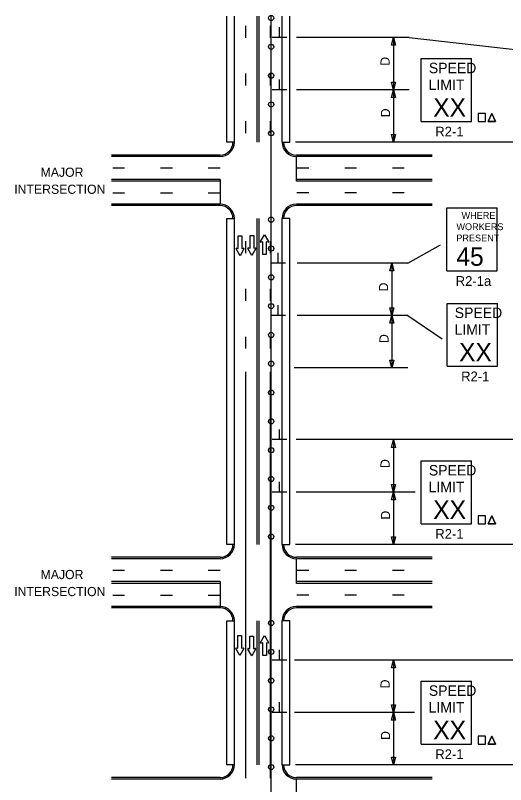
# Model space of a CAD drawing. Extents: x 16735 to 18480, y 5932 to 6927.
# Drawn here: x 16778 to 17153, y 6340 to 6927 of the extents above; entities that cross this region are included whole.
import ezdxf

# ---------------------------------------------------------------- set-up
doc = ezdxf.new("R2010")
doc.units = 0
for name, color, linetype in [('ALI_LEGAL_EX', 7, 'Continuous'), ('MT_SCRATCH_LEVEL_E', 7, 'Continuous'), ('PAVT_EDGE_EX', 7, 'Continuous'), ('TRAFFIC_SIGNS_PR', 7, 'Continuous'), ('TYPICAL_TEXT_DIMEN_PR', 7, 'Continuous')]:
    doc.layers.add(name, color=color, linetype=linetype)

msp = doc.modelspace()

# ---------------------------------------------------------------- linework, layer by layer
at = {"layer": 'ALI_LEGAL_EX'}
for p, q in [((16954.56, 6344.68), (16954.56, 6654.91)), ((16973.51, 6344.68), (16973.51, 6654.91))]:
    msp.add_line(p, q, dxfattribs=at)
for points in [[(16954.56, 6910.12), (16954.56, 6919.23)], [(16973.51, 6910.12), (16973.51, 6919.23)], [(16954.56, 6873.67), (16954.56, 6882.78)], [(16973.51, 6873.67), (16973.51, 6882.78)], [(16954.56, 6837.22), (16954.56, 6846.33)], [(16973.51, 6837.22), (16973.51, 6846.33)], [(16852.86, 6810.71), (16861.98, 6810.71)], [(16889.31, 6810.71), (16898.43, 6810.71)], [(16925.76, 6810.71), (16934.88, 6810.71)], [(16993.62, 6810.85), (17002.73, 6810.85)], [(17030.07, 6810.85), (17039.18, 6810.85)], [(17066.52, 6810.85), (17075.63, 6810.85)], [(16852.86, 6791.76), (16861.98, 6791.76)], [(16889.31, 6791.76), (16898.43, 6791.76)], [(16925.76, 6791.76), (16934.88, 6791.76)], [(16993.62, 6791.9), (17002.73, 6791.9)], [(17030.07, 6791.9), (17039.18, 6791.9)], [(17066.52, 6791.9), (17075.63, 6791.9)], [(16954.56, 6745.63), (16954.56, 6754.74)], [(16973.51, 6745.63), (16973.51, 6754.74)], [(16954.56, 6709.18), (16954.56, 6718.29)], [(16973.51, 6709.18), (16973.51, 6718.29)], [(16954.56, 6672.73), (16954.56, 6681.84)], [(16973.51, 6672.73), (16973.51, 6681.84)], [(16954.56, 6636.28), (16954.56, 6645.39)], [(16973.51, 6636.28), (16973.51, 6645.39)], [(16954.56, 6599.83), (16954.56, 6608.94)], [(16973.51, 6599.83), (16973.51, 6608.94)], [(16852.86, 6503.52), (16861.98, 6503.52)], [(16889.31, 6503.52), (16898.43, 6503.52)], [(16925.76, 6503.52), (16934.88, 6503.52)], [(16993.62, 6503.67), (17002.73, 6503.67)], [(17030.07, 6503.67), (17039.18, 6503.67)], [(17066.52, 6503.67), (17075.63, 6503.67)], [(16852.86, 6484.57), (16861.98, 6484.57)], [(16889.31, 6484.57), (16898.43, 6484.57)], [(16925.76, 6484.57), (16934.88, 6484.57)], [(16993.62, 6484.71), (17002.73, 6484.71)], [(17030.07, 6484.71), (17039.18, 6484.71)], [(17066.52, 6484.71), (17075.63, 6484.71)], [(16954.56, 6454.03), (16954.56, 6463.14)], [(16973.51, 6454.03), (16973.51, 6463.14)], [(16954.56, 6417.58), (16954.56, 6426.69)], [(16973.51, 6417.58), (16973.51, 6426.69)], [(16954.56, 6381.13), (16954.56, 6390.24)], [(16973.51, 6381.13), (16973.51, 6390.24)]]:
    msp.add_lwpolyline(points, dxfattribs=at)
at = {"layer": 'MT_SCRATCH_LEVEL_E'}
for p, q in [((16948.75, 6749.12), (16948.75, 6758.78)), ((16948.75, 6758.78), (16951.47, 6758.78)), ((16948.75, 6749.12), (16948.75, 6758.78)), ((16948.75, 6758.78), (16951.47, 6758.78)), ((16951.47, 6758.78), (16951.47, 6749.12)), ((16951.47, 6758.78), (16951.47, 6749.12)), ((16957.83, 6749.47), (16957.83, 6759.13)), ((16957.83, 6759.13), (16960.56, 6759.13)), ((16957.83, 6749.47), (16957.83, 6759.13)), ((16957.83, 6759.13), (16960.56, 6759.13)), ((16960.56, 6759.13), (16960.56, 6749.47)), ((16960.56, 6759.13), (16960.56, 6749.47)), ((16965.84, 6754.45), (16968.86, 6759.73)), ((16965.84, 6754.45), (16968.86, 6759.73)), ((16968.86, 6759.73), (16971.85, 6754.45)), ((16968.86, 6759.73), (16971.85, 6754.45)), ((16947.45, 6749.35), (16948.75, 6749.12)), ((16947.45, 6749.35), (16948.75, 6749.12)), ((16951.47, 6749.12), (16952.77, 6749.35)), ((16951.47, 6749.12), (16952.77, 6749.35)), ((16959.18, 6743.92), (16956.18, 6749.2)), ((16959.18, 6743.92), (16956.18, 6749.2)), ((16956.53, 6749.7), (16957.83, 6749.47)), ((16956.53, 6749.7), (16957.83, 6749.47)), ((16962.2, 6749.2), (16959.18, 6743.92)), ((16962.2, 6749.2), (16959.18, 6743.92)), ((16960.56, 6749.47), (16961.85, 6749.7)), ((16960.56, 6749.47), (16961.85, 6749.7)), ((16967.48, 6754.18), (16966.18, 6753.95)), ((16967.48, 6754.18), (16966.18, 6753.95)), ((16967.48, 6744.52), (16967.48, 6754.18)), ((16967.48, 6744.52), (16967.48, 6754.18)), ((16971.5, 6753.95), (16970.21, 6754.18)), ((16970.21, 6754.18), (16970.21, 6744.52)), ((16971.5, 6753.95), (16970.21, 6754.18)), ((16970.21, 6754.18), (16970.21, 6744.52)), ((16950.1, 6743.57), (16947.1, 6748.85)), ((16950.1, 6743.57), (16947.1, 6748.85)), ((16953.12, 6748.85), (16950.1, 6743.57)), ((16953.12, 6748.85), (16950.1, 6743.57)), ((16970.21, 6744.52), (16967.48, 6744.52)), ((16970.21, 6744.52), (16967.48, 6744.52)), ((16948.54, 6443.9), (16948.54, 6453.56)), ((16948.54, 6453.56), (16951.27, 6453.56)), ((16948.54, 6443.9), (16948.54, 6453.56)), ((16948.54, 6453.56), (16951.27, 6453.56)), ((16951.27, 6453.56), (16951.27, 6443.9)), ((16951.27, 6453.56), (16951.27, 6443.9)), ((16957.69, 6443.62), (16957.69, 6453.28)), ((16957.69, 6453.28), (16960.42, 6453.28)), ((16957.69, 6443.62), (16957.69, 6453.28)), ((16957.69, 6453.28), (16960.42, 6453.28)), ((16960.42, 6453.28), (16960.42, 6443.62)), ((16960.42, 6453.28), (16960.42, 6443.62)), ((16965.85, 6448.31), (16968.87, 6453.58)), ((16965.85, 6448.31), (16968.87, 6453.58)), ((16968.87, 6453.58), (16971.87, 6448.31)), ((16968.87, 6453.58), (16971.87, 6448.31)), ((16947.25, 6444.13), (16948.54, 6443.9)), ((16947.25, 6444.13), (16948.54, 6443.9)), ((16951.27, 6443.9), (16952.57, 6444.13)), ((16951.27, 6443.9), (16952.57, 6444.13)), ((16956.39, 6443.85), (16957.69, 6443.62)), ((16956.39, 6443.85), (16957.69, 6443.62)), ((16960.42, 6443.62), (16961.71, 6443.85)), ((16960.42, 6443.62), (16961.71, 6443.85)), ((16967.49, 6448.04), (16966.2, 6447.81)), ((16967.49, 6448.04), (16966.2, 6447.81)), ((16967.49, 6438.37), (16967.49, 6448.04)), ((16967.49, 6438.37), (16967.49, 6448.04)), ((16971.52, 6447.81), (16970.22, 6448.04)), ((16970.22, 6448.04), (16970.22, 6438.37)), ((16971.52, 6447.81), (16970.22, 6448.04)), ((16970.22, 6448.04), (16970.22, 6438.37)), ((16949.89, 6438.35), (16946.9, 6443.63)), ((16949.89, 6438.35), (16946.9, 6443.63)), ((16952.92, 6443.63), (16949.89, 6438.35)), ((16952.92, 6443.63), (16949.89, 6438.35)), ((16959.04, 6438.07), (16956.04, 6443.35)), ((16959.04, 6438.07), (16956.04, 6443.35)), ((16962.06, 6443.35), (16959.04, 6438.07)), ((16962.06, 6443.35), (16959.04, 6438.07)), ((16970.22, 6438.37), (16967.49, 6438.37)), ((16970.22, 6438.37), (16967.49, 6438.37))]:
    msp.add_line(p, q, dxfattribs=at)
for centre, start, end in [((16947.4, 6749.01), 80.03619, 209.57516), ((16947.4, 6749.01), 80.03619, 209.57516), ((16952.82, 6749.01), 330.22688, 99.96381), ((16952.82, 6749.01), 330.22688, 99.96381), ((16956.48, 6749.36), 80.03619, 209.57516), ((16956.48, 6749.36), 80.03619, 209.57516), ((16961.9, 6749.36), 330.22688, 99.96381), ((16961.9, 6749.36), 330.22688, 99.96381), ((16966.13, 6754.29), 150.22688, 279.96381), ((16966.13, 6754.29), 150.22688, 279.96381), ((16971.56, 6754.29), 260.03619, 29.57516), ((16971.56, 6754.29), 260.03619, 29.57516), ((16947.19, 6443.79), 80.03619, 209.57516), ((16947.19, 6443.79), 80.03619, 209.57516), ((16952.62, 6443.79), 330.22688, 99.96381), ((16952.62, 6443.79), 330.22688, 99.96381), ((16956.34, 6443.51), 80.03619, 209.57516), ((16956.34, 6443.51), 80.03619, 209.57516), ((16961.76, 6443.51), 330.22688, 99.96381), ((16961.76, 6443.51), 330.22688, 99.96381), ((16966.15, 6448.14), 150.22688, 279.96381), ((16966.15, 6448.14), 150.22688, 279.96381), ((16971.57, 6448.14), 260.03619, 29.57516), ((16971.57, 6448.14), 260.03619, 29.57516)]:
    msp.add_arc(centre, 0.337, start, end, dxfattribs=at)
at = {"layer": 'PAVT_EDGE_EX'}
for p, q in [((16939.98, 6830.39), (16939.98, 6926.6)), ((16945.81, 6830.39), (16945.81, 6926.6)), ((16963.31, 6830.39), (16963.31, 6926.6)), ((16964.77, 6830.39), (16964.77, 6926.6)), ((16973.87, 6153.19), (16973.87, 6927.02)), ((16982.26, 6830.39), (16982.26, 6926.6)), ((16988.09, 6830.39), (16988.09, 6926.6)), ((16945.81, 6830.39), (16939.98, 6830.39)), ((16982.26, 6830.39), (16988.09, 6830.39)), ((16934.88, 6820.55), (16852.04, 6820.55)), ((17096.82, 6820.55), (16993.2, 6820.55)), ((16934.88, 6819.46), (16852.04, 6819.46)), ((16993.2, 6800.5), (16993.2, 6819.46)), ((17096.82, 6819.46), (16993.2, 6819.46)), ((16934.88, 6801.96), (16852.04, 6801.96)), ((16934.88, 6801.96), (16934.88, 6783.01)), ((17096.82, 6801.96), (16993.2, 6801.96)), ((16934.88, 6800.5), (16852.04, 6800.5)), ((17096.82, 6800.5), (16993.2, 6800.5)), ((16934.88, 6783.01), (16852.04, 6783.01)), ((16934.88, 6781.91), (16852.04, 6781.91)), ((17096.82, 6783.01), (16993.2, 6783.01)), ((17096.82, 6781.91), (16993.2, 6781.91)), ((16939.98, 6772.07), (16945.81, 6772.07)), ((16939.98, 6523.21), (16939.98, 6772.07)), ((16945.81, 6523.21), (16945.81, 6772.07)), ((16963.31, 6523.21), (16963.31, 6772.07)), ((16964.77, 6523.21), (16964.77, 6772.07)), ((16988.09, 6772.07), (16982.26, 6772.07)), ((16982.26, 6523.21), (16982.26, 6772.07)), ((16988.09, 6523.21), (16988.09, 6772.07)), ((16945.81, 6523.21), (16939.98, 6523.21)), ((16982.26, 6523.21), (16988.09, 6523.21)), ((16934.88, 6513.37), (16852.04, 6513.37)), ((16934.88, 6512.27), (16852.04, 6512.27)), ((17096.82, 6513.37), (16993.2, 6513.37)), ((17096.82, 6512.27), (16993.2, 6512.27)), ((16993.2, 6493.32), (16993.2, 6512.27)), ((16934.88, 6494.78), (16852.04, 6494.78)), ((16934.88, 6493.32), (16852.04, 6493.32)), ((16934.88, 6494.78), (16934.88, 6474.73)), ((17096.82, 6494.78), (16993.2, 6494.78)), ((17096.82, 6493.32), (16993.2, 6493.32)), ((16934.88, 6475.82), (16852.04, 6475.82)), ((16934.88, 6474.73), (16852.04, 6474.73)), ((17096.82, 6475.82), (16993.2, 6475.82)), ((17096.82, 6474.73), (16993.2, 6474.73)), ((16939.98, 6464.89), (16945.81, 6464.89)), ((16939.98, 6354.95), (16939.98, 6464.89)), ((16945.81, 6354.95), (16945.81, 6464.89)), ((16963.31, 6354.95), (16963.31, 6464.89)), ((16964.77, 6354.95), (16964.77, 6464.89)), ((16988.09, 6464.89), (16982.26, 6464.89)), ((16982.26, 6354.95), (16982.26, 6464.89)), ((16988.09, 6354.95), (16988.09, 6464.89)), ((16945.81, 6354.95), (16939.98, 6354.95)), ((16982.26, 6354.95), (16988.09, 6354.95)), ((16934.88, 6345.11), (16852.04, 6345.11)), ((16934.88, 6344.01), (16852.04, 6344.01)), ((17096.82, 6345.11), (16993.2, 6345.11)), ((16993.2, 6325.06), (16993.2, 6344.01)), ((17096.82, 6344.01), (16993.2, 6344.01))]:
    msp.add_line(p, q, dxfattribs=at)
for centre in [(16973.87, 6925.19), (16973.87, 6903.19), (16973.87, 6881.19), (16973.87, 6859.19), (16973.87, 6837.19), (16973.87, 6771.19), (16973.87, 6749.19), (16973.87, 6727.19), (16973.87, 6705.19), (16973.87, 6683.19), (16973.87, 6661.19), (16973.87, 6639.19), (16973.87, 6617.19), (16973.87, 6595.19), (16973.87, 6573.19), (16973.87, 6551.19), (16973.87, 6529.19), (16973.87, 6463.19), (16973.87, 6441.19), (16973.87, 6419.19), (16973.87, 6397.19), (16973.87, 6375.19), (16973.87, 6353.19)]:
    msp.add_circle(centre, 2, dxfattribs=at)
for centre, radius, start, end in [((16934.88, 6830.39), 10.94, 270, 0), ((16934.88, 6830.39), 9.84, 270, 0), ((16993.2, 6830.39), 10.94, 180, 270), ((16993.2, 6830.39), 9.84, 180, 270), ((16934.88, 6772.07), 10.94, 0, 90), ((16934.88, 6772.07), 9.84, 0, 90), ((16993.2, 6772.07), 10.94, 90, 180), ((16993.2, 6772.07), 9.84, 90, 180), ((16934.88, 6523.21), 10.94, 270, 0), ((16934.88, 6523.21), 9.84, 270, 0), ((16993.2, 6523.21), 10.94, 180, 270), ((16993.2, 6523.21), 9.84, 180, 270), ((16934.88, 6464.89), 10.94, 0, 90), ((16934.88, 6464.89), 9.84, 0, 90), ((16993.2, 6464.89), 10.94, 90, 180), ((16993.2, 6464.89), 9.84, 90, 180), ((16934.88, 6354.95), 10.94, 270, 0), ((16934.88, 6354.95), 9.84, 270, 0), ((16993.2, 6354.95), 10.94, 180, 270), ((16993.2, 6354.95), 9.84, 180, 270)]:
    msp.add_arc(centre, radius, start, end, dxfattribs=at)
at = {"layer": 'TRAFFIC_SIGNS_PR'}
for p, q in [((17088.61, 6894.17), (17127.01, 6894.17)), ((17088.61, 6846.17), (17088.61, 6894.17)), ((17127.01, 6846.17), (17127.01, 6894.17)), ((17088.61, 6846.17), (17127.01, 6846.17)), ((17108.05, 6780.11), (17146.45, 6780.11)), ((17108.05, 6732.11), (17108.05, 6780.11)), ((17146.45, 6732.11), (17146.45, 6780.11)), ((17108.05, 6732.11), (17146.45, 6732.11)), ((17108.37, 6707.24), (17146.77, 6707.24)), ((17108.37, 6659.24), (17108.37, 6707.24)), ((17146.77, 6659.24), (17146.77, 6707.24)), ((17108.37, 6659.24), (17146.77, 6659.24)), ((17088.61, 6586.99), (17127.01, 6586.99)), ((17088.61, 6538.99), (17088.61, 6586.99)), ((17127.01, 6538.99), (17127.01, 6586.99)), ((17088.61, 6538.99), (17127.01, 6538.99)), ((17088.61, 6418.73), (17127.01, 6418.73)), ((17088.61, 6370.73), (17088.61, 6418.73)), ((17127.01, 6370.73), (17127.01, 6418.73)), ((17088.61, 6370.73), (17127.01, 6370.73))]:
    msp.add_line(p, q, dxfattribs=at)
for points in [[(17132.03, 6846.17), (17137.62, 6846.17), (17137.62, 6852.34), (17132.03, 6852.34)], [(17132.03, 6538.99), (17137.62, 6538.99), (17137.62, 6545.16), (17132.03, 6545.16)], [(17132.03, 6370.73), (17137.62, 6370.73), (17137.62, 6376.9), (17132.03, 6376.9)]]:
    msp.add_lwpolyline(points, close=True, dxfattribs=at)
for points in [[(17142.49, 6852.27), (17139.69, 6846.1)], [(17139.69, 6846.1), (17142.49, 6852.27)], [(17145.29, 6846.1), (17142.49, 6852.27)], [(17142.49, 6852.27), (17145.29, 6846.1)], [(17139.69, 6846.1), (17145.29, 6846.1)], [(17145.29, 6846.1), (17139.69, 6846.1)], [(17142.49, 6545.09), (17139.69, 6538.92)], [(17139.69, 6538.92), (17142.49, 6545.09)], [(17145.29, 6538.92), (17142.49, 6545.09)], [(17142.49, 6545.09), (17145.29, 6538.92)], [(17139.69, 6538.92), (17145.29, 6538.92)], [(17145.29, 6538.92), (17139.69, 6538.92)], [(17142.49, 6376.83), (17139.69, 6370.66)], [(17139.69, 6370.66), (17142.49, 6376.83)], [(17145.29, 6370.66), (17142.49, 6376.83)], [(17142.49, 6376.83), (17145.29, 6370.66)], [(17139.69, 6370.66), (17145.29, 6370.66)], [(17145.29, 6370.66), (17139.69, 6370.66)]]:
    msp.add_lwpolyline(points, dxfattribs=at)
at = {"layer": 'TYPICAL_TEXT_DIMEN_PR'}
for p, q in [((16980.33, 6910.4), (16980.33, 6918.18)), ((16985.96, 6910.4), (16974.71, 6910.4)), ((17079.34, 6910.39), (16993.27, 6910.39)), ((17065.72, 6904.53), (17067.29, 6910.39)), ((17067.29, 6910.39), (17068.86, 6904.53)), ((17067.29, 6910.39), (17067.29, 6870.39)), ((17079.34, 6910.39), (17172.69, 6899.57)), ((17067.29, 6904.53), (17065.72, 6904.53)), ((17068.86, 6904.53), (17067.29, 6904.53)), ((16980.33, 6870.4), (16980.33, 6878.18)), ((17067.29, 6870.39), (17065.72, 6876.25)), ((17065.72, 6876.25), (17067.29, 6876.25)), ((17067.29, 6876.25), (17068.86, 6876.25)), ((17068.86, 6876.25), (17067.29, 6870.39)), ((16985.96, 6870.4), (16974.71, 6870.4)), ((17079.34, 6870.39), (16993.27, 6870.39)), ((17065.72, 6864.53), (17067.29, 6870.39)), ((17067.29, 6870.39), (17068.86, 6864.53)), ((17067.29, 6870.39), (17067.29, 6830.39)), ((17067.29, 6870.39), (17067.29, 6870.39)), ((17067.29, 6864.53), (17065.72, 6864.53)), ((17068.86, 6864.53), (17067.29, 6864.53)), ((17067.29, 6830.39), (17065.72, 6836.25)), ((17065.72, 6836.25), (17067.29, 6836.25)), ((17067.29, 6836.25), (17068.86, 6836.25)), ((17068.86, 6836.25), (17067.29, 6830.39)), ((17417.27, 6830.39), (16992.61, 6830.39)), ((17067.29, 6830.39), (17067.29, 6830.39)), ((17078.22, 6738.03), (17103.26, 6751.91)), ((16979.21, 6738.04), (16979.21, 6745.82)), ((16984.83, 6738.04), (16973.58, 6738.04)), ((17078.22, 6738.03), (16993.8, 6738.03)), ((17064.6, 6732.17), (17066.17, 6738.03)), ((17066.17, 6738.03), (17067.74, 6732.17)), ((17066.17, 6738.03), (17066.17, 6698.03)), ((17066.17, 6732.17), (17064.6, 6732.17)), ((17067.74, 6732.17), (17066.17, 6732.17)), ((16979.21, 6698.04), (16979.21, 6705.82)), ((17066.17, 6698.03), (17064.6, 6703.9)), ((17064.6, 6703.9), (17066.17, 6703.9)), ((17066.17, 6703.9), (17067.74, 6703.9)), ((17067.74, 6703.9), (17066.17, 6698.03)), ((16984.83, 6698.04), (16973.58, 6698.04)), ((17078.22, 6698.03), (16993.8, 6698.03)), ((17064.6, 6692.17), (17066.17, 6698.03)), ((17066.17, 6698.03), (17067.74, 6692.17)), ((17066.17, 6698.03), (17066.17, 6658.03)), ((17066.17, 6698.03), (17066.17, 6698.03)), ((17078.22, 6698.03), (17104.47, 6680.25)), ((17066.17, 6692.17), (17064.6, 6692.17)), ((17067.74, 6692.17), (17066.17, 6692.17)), ((17066.17, 6658.03), (17064.6, 6663.9)), ((17064.6, 6663.9), (17066.17, 6663.9)), ((17066.17, 6663.9), (17067.74, 6663.9)), ((17067.74, 6663.9), (17066.17, 6658.03)), ((17078.22, 6658.03), (16991.48, 6658.03)), ((17066.17, 6658.03), (17066.17, 6658.03)), ((16980.33, 6603.21), (16980.33, 6611)), ((16985.96, 6603.21), (16974.71, 6603.21)), ((17171.43, 6603.21), (16993, 6603.21)), ((17065.72, 6597.35), (17067.29, 6603.21)), ((17067.29, 6603.21), (17068.86, 6597.35)), ((17067.29, 6603.21), (17067.29, 6563.21)), ((17067.29, 6597.35), (17065.72, 6597.35)), ((17068.86, 6597.35), (17067.29, 6597.35)), ((16980.33, 6563.21), (16980.33, 6571)), ((17067.29, 6563.21), (17065.72, 6569.07)), ((17065.72, 6569.07), (17067.29, 6569.07)), ((17067.29, 6569.07), (17068.86, 6569.07)), ((17068.86, 6569.07), (17067.29, 6563.21)), ((16985.96, 6563.21), (16974.71, 6563.21)), ((17083.98, 6563.21), (16993, 6563.21)), ((17065.72, 6557.35), (17067.29, 6563.21)), ((17067.29, 6563.21), (17068.86, 6557.35)), ((17067.29, 6563.21), (17067.29, 6523.21)), ((17067.29, 6563.21), (17067.29, 6563.21)), ((17067.29, 6557.35), (17065.72, 6557.35)), ((17068.86, 6557.35), (17067.29, 6557.35)), ((17067.29, 6523.21), (17065.72, 6529.07)), ((17065.72, 6529.07), (17067.29, 6529.07)), ((17067.29, 6529.07), (17068.86, 6529.07)), ((17068.86, 6529.07), (17067.29, 6523.21)), ((17408.46, 6523.21), (16992.61, 6523.21)), ((17067.29, 6523.21), (17067.29, 6523.21)), ((16980.33, 6434.95), (16980.33, 6442.74)), ((16985.96, 6434.95), (16974.71, 6434.95)), ((17170.95, 6434.95), (16991.66, 6434.95)), ((17065.72, 6429.09), (17067.29, 6434.95)), ((17067.29, 6434.95), (17068.86, 6429.09)), ((17067.29, 6434.95), (17067.29, 6394.95)), ((17067.29, 6429.09), (17065.72, 6429.09)), ((17068.86, 6429.09), (17067.29, 6429.09)), ((16980.33, 6394.95), (16980.33, 6402.74)), ((17067.29, 6394.95), (17065.72, 6400.81)), ((17065.72, 6400.81), (17067.29, 6400.81)), ((17067.29, 6400.81), (17068.86, 6400.81)), ((17068.86, 6400.81), (17067.29, 6394.95)), ((16985.96, 6394.95), (16974.71, 6394.95)), ((17083.5, 6394.95), (16991.66, 6394.95)), ((17065.72, 6389.09), (17067.29, 6394.95)), ((17067.29, 6394.95), (17068.86, 6389.09)), ((17067.29, 6394.95), (17067.29, 6354.95)), ((17067.29, 6394.95), (17067.29, 6394.95)), ((17067.29, 6389.09), (17065.72, 6389.09)), ((17068.86, 6389.09), (17067.29, 6389.09)), ((17067.29, 6354.95), (17065.72, 6360.81)), ((17065.72, 6360.81), (17067.29, 6360.81)), ((17067.29, 6360.81), (17068.86, 6360.81)), ((17068.86, 6360.81), (17067.29, 6354.95)), ((17333.74, 6354.95), (16992.61, 6354.95)), ((17067.29, 6354.95), (17067.29, 6354.95))]:
    msp.add_line(p, q, dxfattribs=at)

# ---------------------------------------------------------------- texts
at = {"layer": 'TRAFFIC_SIGNS_PR'}
for s, height, p in [('SPEED', 8, (17094.38, 6883.03)), ('LIMIT', 8, (17094.22, 6870.23)), ('XX', 14.031, (17097.73, 6849.93)), ('R2-1', 7.44, (17099.29, 6834.73)), ('WHERE', 5.2, (17119.36, 6771.8)), ('WORKERS', 5.2, (17115.43, 6763.2)), ('PRESENT', 5.2, (17115.37, 6754.6)), ('45', 14.031, (17115.36, 6735.97)), ('R2-1a', 7.44, (17114.9, 6720.67)), ('SPEED', 8, (17114.14, 6696.1)), ('LIMIT', 8, (17113.98, 6683.3)), ('XX', 14.031, (17117.48, 6663)), ('R2-1', 7.44, (17119.05, 6647.8)), ('SPEED', 8, (17094.38, 6575.85)), ('LIMIT', 8, (17094.22, 6563.05)), ('XX', 14.031, (17097.73, 6542.74)), ('R2-1', 7.44, (17099.29, 6527.55)), ('SPEED', 8, (17094.38, 6407.59)), ('LIMIT', 8, (17094.22, 6394.79)), ('XX', 14.031, (17097.73, 6374.49)), ('R2-1', 7.44, (17099.29, 6359.29))]:
    msp.add_text(s, height=height, dxfattribs=at).set_placement(p)
at = {"layer": 'TYPICAL_TEXT_DIMEN_PR'}
for s, rotation, p in [('D', 90, (17064.39, 6888.75)), ('D', 90, (17064.73, 6849.36)), ('MAJOR', 360, (16797.76, 6803.93)), ('INTERSECTION', 360, (16777.63, 6790.93)), ('D', 90, (17063.26, 6716.39)), ('D', 90, (17063.61, 6677)), ('D', 90, (17064.39, 6581.56)), ('D', 90, (17064.73, 6542.17)), ('MAJOR', 360, (16797.76, 6496.74)), ('INTERSECTION', 360, (16777.63, 6483.74)), ('D', 90, (17064.39, 6413.31)), ('D', 90, (17064.73, 6373.92))]:
    msp.add_text(s, height=7, rotation=rotation, dxfattribs=at).set_placement(p)

doc.saveas('drawing.dxf')
